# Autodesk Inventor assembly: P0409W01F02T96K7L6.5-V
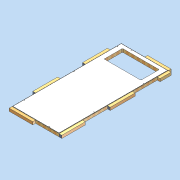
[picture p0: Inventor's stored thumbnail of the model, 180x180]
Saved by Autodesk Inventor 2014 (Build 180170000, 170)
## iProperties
Created: 2011-04
Part Number: P0409W01F02T96K7L6.5-V
Document SubType Name: Assembly
Designer: david.appleford
Description: 1w x 2.25w  01 Panel - 7 Locks 6.5 Lugs
Mass: 220837 g
Surface Area: 72891.7 cm^2
Volume: 231077 cm^3
Density: 0.955685 g/cm^3
Cost Center: £185.00
Justset: False
Title: 1w x 2w  01 Panel - 6 Locks 6 Lugs
Author: david.appleford
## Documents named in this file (5)
- C:\Documents and Settings\john.everitt\Local Settings\My Documents\Vault\Production MkII\Virtual Elements\Virtual Walls\Virtual Timber + MgO\P0409W01F02T96K7L6.5-V.iam
- C:\Documents and Settings\john.everitt\Local Settings\My Documents\Vault\Production MkII\VIRTUAL ELEMENTS\Virtual Lugs\Superceded Lugs\LA02C3V.ipt
- C:\Documents and Settings\john.everitt\Local Settings\My Documents\Vault\Production MkII\VIRTUAL ELEMENTS\Virtual Lugs\Superceded Lugs\LA02M3V.ipt
- C:\Documents and Settings\john.everitt\Local Settings\My Documents\Vault\Production MkII\VIRTUAL ELEMENTS\Virtual Lugs\Superceded Lugs\LA01C3V.ipt
- C:\Documents and Settings\john.everitt\Local Settings\My Documents\Vault\Production MkII\Virtual Elements\Virtual Walls\Virtual Timber + MgO\P0409W01F02T96K7-V.ipt
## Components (8 placed, 4 different names)
1. P0409W01F02T96K7-V:1 — Mate:1, Flush:1, Flush:2, Mate:2, Flush:3, Flush:4, Mate:4, Flush:7, Flush:8, Mate:5, Mate:6, Flush:9, Flush:10, Mate:7, Flush:11, Mate:14, Flush:12, Flush:13
2. LA02C3V:1 — Mate:1, Flush:1, Flush:2, Mate:9, Mate:13
3. LA02C3V:2 — Mate:2, Flush:3, Flush:4
4. LA02C3V:3 — Mate:4, Flush:7, Flush:8
5. LA02M3V:5 — Mate:6, Flush:9, Mate:12
6. LA02M3V:2 — Mate:5, Flush:10, Mate:12, Mate:13
7. LA02M3V:4 — Mate:7, Flush:11, Mate:9
8. LA01C3V:1 — Mate:14, Flush:12, Flush:13
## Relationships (21: Flush 11, Mate 10)
- Mate:1: P0409W01F02T96K7-V:1 ↔ LA02C3V:1
- Flush:1: P0409W01F02T96K7-V:1 ↔ LA02C3V:1
- Flush:2: P0409W01F02T96K7-V:1 ↔ LA02C3V:1
- Mate:2: P0409W01F02T96K7-V:1 ↔ LA02C3V:2
- Flush:3: P0409W01F02T96K7-V:1 ↔ LA02C3V:2
- Flush:4: P0409W01F02T96K7-V:1 ↔ LA02C3V:2
- Mate:4: P0409W01F02T96K7-V:1 ↔ LA02C3V:3
- Flush:7: P0409W01F02T96K7-V:1 ↔ LA02C3V:3
- Flush:8: P0409W01F02T96K7-V:1 ↔ LA02C3V:3
- Mate:5: P0409W01F02T96K7-V:1 ↔ LA02M3V:2
- Mate:6: P0409W01F02T96K7-V:1 ↔ LA02M3V:5
- Flush:9: P0409W01F02T96K7-V:1 ↔ LA02M3V:5
- Flush:10: P0409W01F02T96K7-V:1 ↔ LA02M3V:2
- Mate:7: P0409W01F02T96K7-V:1 ↔ LA02M3V:4
- Flush:11: P0409W01F02T96K7-V:1 ↔ LA02M3V:4
- Mate:9: LA02C3V:1 ↔ LA02M3V:4
- Mate:12: LA02M3V:5 ↔ LA02M3V:2
- Mate:13: LA02C3V:1 ↔ LA02M3V:2
- Mate:14: P0409W01F02T96K7-V:1 ↔ LA01C3V:1
- Flush:12: P0409W01F02T96K7-V:1 ↔ LA01C3V:1
- Flush:13: P0409W01F02T96K7-V:1 ↔ LA01C3V:1
## Named parameters: t = 1 mm, Cl = 2 mm
